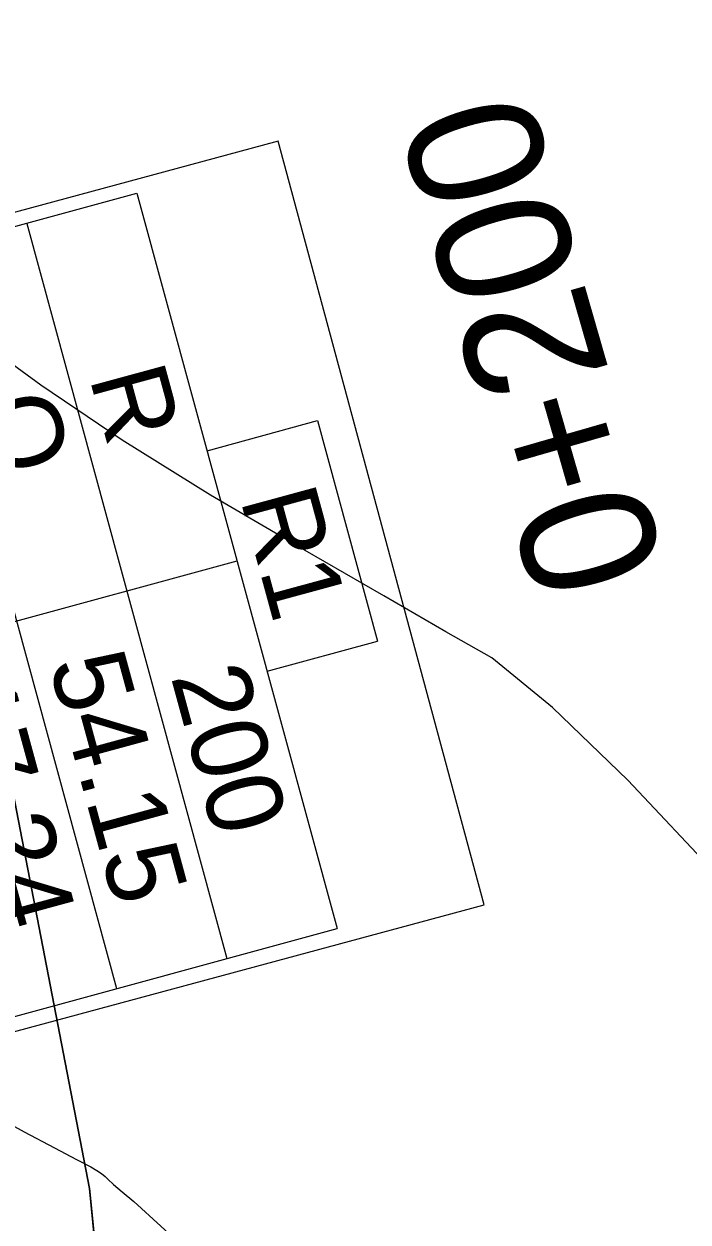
# Model space of a CAD drawing. Extents: x -574342 to -508101, y -1143544 to -1123894.
# Drawn here: x -508506.16 to -508486.42, y -1143313.1 to -1143277.46 of the extents above; entities that cross this region are included whole.
import ezdxf

# ---------------------------------------------------------------- set-up
doc = ezdxf.new("R2010")
doc.units = 0
for name, color, linetype in [('01_PARCELY_NAVRH_PC', 7, 'Continuous'), ('01_PARCELY_NAVRH_ŽP', 7, 'Continuous'), ('18', 7, 'Continuous'), ('42', 7, 'Continuous'), ('SO 101_popis oblouku', 7, 'Continuous'), ('VRST VEDL', 7, 'Continuous')]:
    doc.layers.add(name, color=color, linetype=linetype)

msp = doc.modelspace()

# ---------------------------------------------------------------- linework, layer by layer
msp.add_lwpolyline([(-508519.625, -1143286.627), (-508513.495, -1143309.334), (-508492.475, -1143303.66), (-508498.604, -1143280.952)], close=True)
at = {"layer": '01_PARCELY_NAVRH_PC'}
msp.add_lwpolyline([(-508491.36, -1143454.58), (-508498.26, -1143372.94), (-508504.21, -1143312.1), (-508506.89, -1143298.29), (-508511.25, -1143285.64), (-508519.86, -1143267.33), (-508524.26, -1143263.08), (-508531.16, -1143250.06)], dxfattribs=at)
msp.add_lwpolyline([(-508491.36, -1143454.58), (-508498.26, -1143372.94), (-508504.21, -1143312.1), (-508506.89, -1143298.29), (-508511.25, -1143285.64), (-508519.86, -1143267.33), (-508524.26, -1143263.08), (-508531.16, -1143250.06)], dxfattribs=at)
at = {"layer": '01_PARCELY_NAVRH_ŽP'}
msp.add_lwpolyline([(-508425.23, -1143400.39), (-508448.26, -1143343.08), (-508432.21, -1143324.29), (-508434.31, -1143320.59), (-508441.9, -1143297.61), (-508445.4, -1143275.01), (-508446.02, -1143260.22), (-508475.11, -1143263.39), (-508493.5, -1143263.3), (-508514.56, -1143259.91), (-508521.01, -1143259.29), (-508524.26, -1143263.08), (-508519.86, -1143267.33), (-508511.25, -1143285.64), (-508506.89, -1143298.29), (-508504.21, -1143312.1), (-508498.26, -1143372.94), (-508491.36, -1143454.58)], dxfattribs=at)
at = {"layer": '42'}
for points in [[(-508495.7, -1143263.7), (-508516.42, -1143260.79), (-508519.86, -1143267.33), (-508511.25, -1143285.64), (-508506.89, -1143298.29), (-508504.21, -1143312.1)], [(-508495.7, -1143263.7), (-508516.42, -1143260.79), (-508519.86, -1143267.33), (-508511.25, -1143285.64), (-508506.89, -1143298.29), (-508504.21, -1143312.1)], [(-508504.21, -1143312.1), (-508501.69, -1143337.29), (-508498.26, -1143372.94), (-508494.88, -1143409.3), (-508491.01, -1143461.13), (-508489.31, -1143484.85), (-508488.03, -1143504.43), (-508488.95, -1143532.56), (-508489.059, -1143536.058)], [(-508504.21, -1143312.1), (-508501.69, -1143337.29), (-508498.26, -1143372.94), (-508494.88, -1143409.3), (-508491.01, -1143461.13), (-508489.31, -1143484.85), (-508488.03, -1143504.43), (-508488.95, -1143532.56), (-508489.059, -1143536.058)]]:
    msp.add_lwpolyline(points, dxfattribs=at)
at = {"layer": 'SO 101_popis oblouku'}
for p, q in [((-508519.204, -1143286.964), (-508502.801, -1143282.499)), ((-508502.801, -1143282.499), (-508496.847, -1143304.37)), ((-508506.081, -1143283.392), (-508500.128, -1143305.263)), ((-508509.362, -1143284.285), (-508503.409, -1143306.156)), ((-508500.717, -1143290.154), (-508497.436, -1143289.261)), ((-508497.436, -1143289.261), (-508495.65, -1143295.822)), ((-508516.227, -1143297.899), (-508499.824, -1143293.434)), ((-508498.931, -1143296.715), (-508495.65, -1143295.822)), ((-508513.251, -1143308.835), (-508496.847, -1143304.37))]:
    msp.add_line(p, q, dxfattribs=at)
at = {"layer": 'VRST VEDL'}
for points in [[(-508485.517, -1143302.811), (-508488.203, -1143299.954), (-508490.448, -1143297.79), (-508492.253, -1143296.32), (-508493.617, -1143295.542), (-508495.466, -1143294.476), (-508497.8, -1143293.121), (-508500.618, -1143291.478), (-508503.24, -1143289.839), (-508505.664, -1143288.205), (-508507.892, -1143286.577)], [(-508506.819, -1143310.045), (-508506.155, -1143310.42), (-508505.254, -1143310.89), (-508504.595, -1143311.237), (-508504.176, -1143311.461), (-508503.999, -1143311.562), (-508503.855, -1143311.657), (-508503.744, -1143311.746), (-508503.666, -1143311.829), (-508503.498, -1143311.981), (-508503.241, -1143312.202), (-508502.895, -1143312.491), (-508500.491, -1143314.694)]]:
    msp.add_lwpolyline(points, dxfattribs=at)

# ---------------------------------------------------------------- texts
at = {"layer": '18'}
msp.add_text('0+200', height=4, rotation=106.0424, dxfattribs=at).set_placement((-508487.052, -1143293.72))
at = {"layer": 'SO 101_popis oblouku'}
for s, height, p in [('R', 2.267, (-508504.224, -1143287.976)), ('O', 2.267, (-508507.533, -1143288.765)), ('R1', 2.2667, (-508499.736, -1143291.598)), ('54.15', 2.2667, (-508505.431, -1143296.484)), ('200', 2.2667, (-508501.803, -1143296.867)), ('17.24', 2.2667, (-508508.76, -1143297.202))]:
    msp.add_text(s, height=height, rotation=285.222, dxfattribs=at).set_placement(p)

doc.saveas('drawing.dxf')
